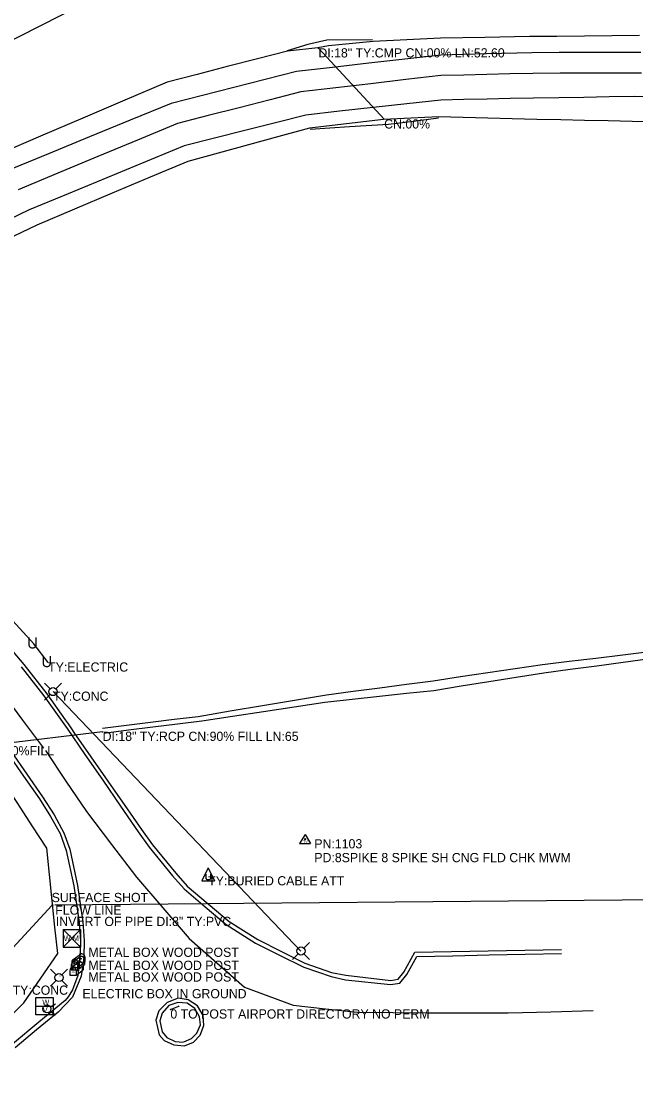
# Model space of a CAD drawing. Extents: x 1707085 to 1720058, y 548761 to 560063.
# Drawn here: x 1711655 to 1711989, y 548951 to 549528 of the extents above; entities that cross this region are included whole.
import ezdxf

# ---------------------------------------------------------------- set-up
doc = ezdxf.new("R2010")
doc.units = 0
for name, color, linetype in [('3', 7, 'Continuous'), ('Default', 7, 'Continuous'), ('R_Draft', 7, 'Continuous'), ('R_Horz Alg Annot', 7, 'Continuous'), ('R_Water Annot', 7, 'Continuous'), ('S_CROSS_DRAIN_ANNOT', 7, 'Continuous'), ('S_CURB', 7, 'Continuous'), ('S_DRG_PT_SYM', 7, 'Continuous'), ('S_EDGE_PAVEMENT', 7, 'Continuous'), ('S_GRD_PT_SYM', 7, 'Continuous'), ('S_MAILBOX', 7, 'Continuous'), ('S_MAILBOX_ANNOT', 7, 'Continuous'), ('S_MANHOLE_ANNOT', 7, 'Continuous'), ('S_MISC_STRUCTURES_ANNOT', 7, 'Continuous'), ('S_MISC_TOPO_POINT', 7, 'Continuous'), ('S_MSC_PT_SYM', 7, 'Continuous'), ('S_PAVEMENT_CROWN', 7, 'Continuous'), ('S_SANITARY_SEWER', 7, 'Continuous'), ('S_SANITARY_SEWER_ANNOT', 7, 'Continuous'), ('S_SECONDARY_CTL_ANNOT', 7, 'Continuous'), ('S_SIDE_DRAIN_ANNOT', 7, 'Continuous'), ('S_SIGN_ANNOT', 7, 'Continuous'), ('S_UNDERGROUND_CABLE', 7, 'Continuous'), ('S_UNDERGROUND_CABLE_ANNOT', 7, 'Continuous'), ('S_UTILITY_POLE', 7, 'Continuous'), ('S_UTILITY_POLE_ANNOT', 7, 'Continuous'), ('S_UTL_PT_SYM', 7, 'Continuous')]:
    doc.layers.add(name, color=color, linetype=linetype)

msp = doc.modelspace()

# ---------------------------------------------------------------- linework, layer by layer
for points in [[(1711990.87, 549520.44), (1711975.92, 549520.28), (1711960.98, 549520.11), (1711946.04, 549519.95), (1711931.09, 549519.79), (1711906.92, 549519.41), (1711882.74, 549519.03), (1711864.5, 549518.06), (1711846.26, 549517.1), (1711821.98, 549514.8), (1711816.17, 549513.75), (1711799.76, 549511.86), (1711783.39, 549507.68), (1711767.02, 549503.49), (1711750.66, 549499.3), (1711734.29, 549495.11), (1711711.39, 549485.32), (1711688.5, 549475.53), (1711665.6, 549465.74), (1711642.7, 549455.95)], [(1711845.91, 549518.04), (1711821.14, 549517.95), (1711810.67, 549515.52), (1711799.44, 549512.16)], [(1712004.2, 549473.45), (1711986.91, 549473.71), (1711973.98, 549473.99), (1711961.05, 549474.27), (1711948.12, 549474.55), (1711935.19, 549474.82), (1711921.85, 549475.16), (1711908.5, 549475.49), (1711895.16, 549475.83), (1711881.82, 549476.16), (1711866.84, 549475.51), (1711851.86, 549474.86), (1711831.73, 549472.48), (1711811.6, 549470.1), (1711795.09, 549465.58), (1711778.57, 549461.07), (1711762.05, 549456.55), (1711745.54, 549452.04), (1711725.02, 549443.4), (1711704.51, 549434.77), (1711683.99, 549426.13), (1711663.48, 549417.49), (1711646.94, 549409.44)], [(1711881.74, 549475.45), (1711868.18, 549473.79), (1711854.61, 549472.12), (1711833.3, 549470.74), (1711812, 549469.35)], [(1711699.23, 549144.27), (1711712.22, 549145.85), (1711725.21, 549147.44), (1711738.2, 549149.02), (1711751.19, 549150.6), (1711768.63, 549153.55), (1711786.06, 549156.5), (1711803.49, 549159.45), (1711820.93, 549162.4), (1711835.42, 549164.3), (1711849.91, 549166.21), (1711864.4, 549168.11), (1711878.89, 549170.01), (1711893.72, 549172.21), (1711908.56, 549174.4), (1711923.39, 549176.6), (1711938.23, 549178.8), (1711952.76, 549180.55), (1711967.3, 549182.3), (1711981.83, 549184.05), (1711996.36, 549185.8)], [(1711699.96, 549141.57), (1711713.26, 549143.24), (1711726.56, 549144.92), (1711739.86, 549146.59), (1711753.16, 549148.27), (1711769.87, 549150.8), (1711786.58, 549153.33), (1711803.29, 549155.86), (1711819.99, 549158.39), (1711834.8, 549159.98), (1711849.61, 549161.57), (1711864.41, 549163.16), (1711879.22, 549164.75), (1711894.14, 549167.13), (1711909.05, 549169.52), (1711923.96, 549171.9), (1711938.88, 549174.28), (1711953.29, 549176.2), (1711967.7, 549178.13), (1711982.11, 549180.05), (1711996.52, 549181.97)], [(1711611.51, 548950.56), (1711622.73, 548961.7), (1711633.95, 548972.84), (1711645.16, 548983.98), (1711656.38, 548995.12), (1711665.63, 549008.46), (1711674.87, 549021.8), (1711673.4, 549036.12), (1711671.93, 549050.43), (1711670.45, 549064.75), (1711668.98, 549079.06), (1711661.08, 549091.17), (1711653.18, 549103.27), (1711645.28, 549115.38), (1711637.38, 549127.48)]]:
    msp.add_lwpolyline(points)
at = {"layer": '3'}
for p, q in [((1711816.48, 549513.49), (1711852.23, 549474.89)), ((1711699.29, 549142.3), (1711634.65, 549134.46))]:
    msp.add_line(p, q, dxfattribs=at)
at = {"layer": 'R_Draft'}
for p, q in [((1711809.29, 549086.54), (1711806.28, 549081.59)), ((1711809.29, 549086.54), (1711812.23, 549081.59)), ((1711806.28, 549081.59), (1711812.23, 549081.59))]:
    msp.add_line(p, q, dxfattribs=at)
for radius in [0.311, 0.183, 0.103]:
    msp.add_circle((1711809.29, 549083.93), radius, dxfattribs=at)
at = {"layer": 'R_Horz Alg Annot'}
msp.add_line((1711736.08, 548991.51), (1711740.62, 548993.18), dxfattribs=at)
at = {"layer": 'R_Water Annot'}
for p, q in [((1711677.92, 549034.85), (1711687.26, 549034.85)), ((1711677.92, 549034.85), (1711677.92, 549025.36)), ((1711677.92, 549034.85), (1711687.26, 549025.36)), ((1711687.26, 549034.85), (1711677.92, 549025.36)), ((1711687.26, 549034.85), (1711687.26, 549025.36)), ((1711677.92, 549025.36), (1711687.26, 549025.36)), ((1711662.94, 548997.98), (1711672.36, 548997.98)), ((1711662.94, 548988.56), (1711662.94, 548997.98)), ((1711670.93, 548992.83), (1711673.75, 548994.56)), ((1711672.36, 548997.98), (1711672.36, 548988.56)), ((1711662.94, 548993.29), (1711672.36, 548993.29)), ((1711672.36, 548988.56), (1711662.94, 548988.56)), ((1711670.81, 548990.52), (1711673.71, 548988.59))]:
    msp.add_line(p, q, dxfattribs=at)
msp.add_circle((1711669.03, 548991.77), 2.18, dxfattribs=at)
at = {"layer": 'S_CURB'}
for points in [[(1711643.49, 549193.99), (1711656.55, 549178.8), (1711668.9, 549162.86), (1711679.01, 549148.77), (1711680.5, 549146.55), (1711682.42, 549143.88), (1711683.66, 549141.82), (1711692.86, 549128.64), (1711702.07, 549115.47), (1711711.27, 549102.3), (1711720.47, 549089.12), (1711726.34, 549080.94), (1711738.97, 549065.42), (1711745.16, 549058.45), (1711756.58, 549048.87), (1711768, 549039.3), (1711783.63, 549029.35), (1711796.41, 549023), (1711809.18, 549016.65), (1711823.62, 549011.55), (1711831.39, 549009.99), (1711855.77, 549007.12), (1711859.78, 549007.86), (1711862.83, 549011.68), (1711868.88, 549022.61), (1711888.8, 549022.97), (1711908.72, 549023.34), (1711928.64, 549023.71), (1711948.55, 549024.08)], [(1711647.77, 549130.54), (1711656.35, 549118.18), (1711664.93, 549105.82), (1711670.98, 549096.33), (1711676.24, 549086.98), (1711679.53, 549077.84), (1711683.59, 549058.51), (1711686.44, 549038.73), (1711687.17, 549028.74), (1711686.91, 549019.68), (1711685.72, 549009.93), (1711682.92, 549002.12), (1711681.49, 548999.76), (1711680.6, 548998.23), (1711678.97, 548996.32), (1711664.62, 548984.47), (1711650.28, 548972.62)], [(1711743.41, 548973.85), (1711747.61, 548975.66), (1711750.46, 548978.48), (1711752.39, 548983.04), (1711751.99, 548987.44), (1711749.43, 548991.89), (1711745.12, 548994.78), (1711740.05, 548995.29), (1711735.3, 548993.56), (1711731.57, 548989.46), (1711730.29, 548985.31), (1711731.58, 548979.24), (1711734.18, 548976.17), (1711738.72, 548973.98), (1711743.06, 548973.69)]]:
    msp.add_lwpolyline(points, dxfattribs=at)
at = {"layer": 'S_DRG_PT_SYM'}
for points in [[(1711816.48, 549513.49), (1711816.48, 549513.54), (1711816.48, 549513.49), (1711816.43, 549513.49), (1711816.48, 549513.49), (1711816.48, 549513.44), (1711816.48, 549513.49), (1711816.53, 549513.49)], [(1711852.23, 549474.89), (1711852.23, 549474.94), (1711852.23, 549474.89), (1711852.18, 549474.89), (1711852.23, 549474.89), (1711852.23, 549474.84), (1711852.23, 549474.89), (1711852.28, 549474.89)], [(1711699.29, 549142.3), (1711699.29, 549142.35), (1711699.29, 549142.3), (1711699.24, 549142.3), (1711699.29, 549142.3), (1711699.29, 549142.25), (1711699.29, 549142.3), (1711699.34, 549142.3)]]:
    msp.add_lwpolyline(points, dxfattribs=at)
at = {"layer": 'S_EDGE_PAVEMENT'}
for points in [[(1711991.65, 549511.21), (1711976.87, 549511.17), (1711962.09, 549511.13), (1711947.31, 549511.09), (1711932.53, 549511.05), (1711907.8, 549510.43), (1711883.06, 549509.81), (1711863.45, 549507.57), (1711843.83, 549505.32), (1711824.22, 549503.07), (1711804.61, 549500.83), (1711787.58, 549496.52), (1711770.54, 549492.2), (1711753.51, 549487.89), (1711736.48, 549483.57), (1711714.29, 549474.46), (1711692.1, 549465.34), (1711669.9, 549456.22), (1711647.71, 549447.1)], [(1711991.65, 549511.21), (1711976.87, 549511.17), (1711962.09, 549511.13), (1711947.31, 549511.09), (1711932.53, 549511.05), (1711907.8, 549510.43), (1711883.06, 549509.81), (1711863.45, 549507.57), (1711843.83, 549505.32), (1711824.22, 549503.07), (1711804.61, 549500.83), (1711787.58, 549496.52), (1711770.54, 549492.2), (1711753.51, 549487.89), (1711736.48, 549483.57), (1711714.29, 549474.46), (1711692.1, 549465.34), (1711669.9, 549456.22), (1711647.71, 549447.1)], [(1712004.79, 549487.15), (1711988.04, 549487.23), (1711974.37, 549487.02), (1711960.71, 549486.81), (1711947.04, 549486.59), (1711933.37, 549486.38), (1711920.76, 549486.12), (1711908.15, 549485.86), (1711895.54, 549485.61), (1711882.94, 549485.35), (1711864.61, 549483.31), (1711846.28, 549481.27), (1711827.96, 549479.23), (1711809.63, 549477.19), (1711793.12, 549473.02), (1711776.6, 549468.85), (1711760.09, 549464.68), (1711743.58, 549460.51), (1711722.54, 549451.81), (1711701.51, 549443.1), (1711680.47, 549434.39), (1711659.43, 549425.69), (1711643, 549417.91)], [(1712004.79, 549487.15), (1711988.04, 549487.23), (1711974.37, 549487.02), (1711960.71, 549486.81), (1711947.04, 549486.59), (1711933.37, 549486.38), (1711920.76, 549486.12), (1711908.15, 549485.86), (1711895.54, 549485.61), (1711882.94, 549485.35), (1711864.61, 549483.31), (1711846.28, 549481.27), (1711827.96, 549479.23), (1711809.63, 549477.19), (1711793.12, 549473.02), (1711776.6, 549468.85), (1711760.09, 549464.68), (1711743.58, 549460.51), (1711722.54, 549451.81), (1711701.51, 549443.1), (1711680.47, 549434.39), (1711659.43, 549425.69), (1711643, 549417.91)], [(1711655.07, 549177.46), (1711667.27, 549161.8), (1711679.95, 549144.01), (1711689.62, 549129.98), (1711699.3, 549115.95), (1711708.97, 549101.92), (1711718.65, 549087.89), (1711724.51, 549079.61), (1711737.29, 549064.07), (1711743.56, 549057.03), (1711754.93, 549047.27), (1711766.31, 549037.51), (1711782.34, 549027.48), (1711795.43, 549020.97), (1711808.51, 549014.46), (1711823.52, 549009.4), (1711831.16, 549007.62), (1711855.6, 549004.99), (1711860.69, 549005.72), (1711864.58, 549010.42), (1711869.98, 549020.25), (1711889.61, 549020.66), (1711909.24, 549021.07), (1711928.87, 549021.48), (1711948.5, 549021.89)], [(1711649.62, 549131.57), (1711658.16, 549119.26), (1711666.7, 549106.96), (1711672.87, 549097.14), (1711678.17, 549087.42), (1711681.43, 549078.5), (1711685.63, 549058.79), (1711688.57, 549038.95), (1711689.2, 549028.92), (1711689.03, 549019.62), (1711687.63, 549009.61), (1711682.91, 548998.14), (1711675.11, 548989.89), (1711663.4, 548980.29), (1711651.69, 548970.68)]]:
    msp.add_lwpolyline(points, dxfattribs=at)
msp.add_lwpolyline([(1711743.71, 548971.66), (1711748.56, 548973.66), (1711752.34, 548977.43), (1711754.29, 548982.69), (1711753.83, 548988.19), (1711750.73, 548993.48), (1711745.73, 548996.7), (1711740.37, 548997.53), (1711734.33, 548995.26), (1711729.89, 548990.66), (1711728.18, 548985.56), (1711729.9, 548977.73), (1711732.78, 548974.64), (1711737.87, 548972.17)], close=True, dxfattribs=at)
at = {"layer": 'S_GRD_PT_SYM'}
for points in [[(1711671.61, 549047.9), (1711671.61, 549047.95), (1711671.61, 549047.9), (1711671.56, 549047.9), (1711671.61, 549047.9), (1711671.61, 549047.85), (1711671.61, 549047.9), (1711671.66, 549047.9)], [(1711673.3, 549048.29), (1711673.3, 549048.34), (1711673.3, 549048.29), (1711673.25, 549048.29), (1711673.3, 549048.29), (1711673.3, 549048.24), (1711673.3, 549048.29), (1711673.35, 549048.29)]]:
    msp.add_lwpolyline(points, dxfattribs=at)
at = {"layer": 'S_MAILBOX'}
for p, q in [((1711682.08, 549013.97), (1711686.22, 549017.08)), ((1711682.49, 549017.04), (1711682.49, 549014.32)), ((1711682.78, 549016.94), (1711686.91, 549020.04)), ((1711683.05, 549018.31), (1711687.18, 549021.42)), ((1711685.82, 549014.32), (1711689.61, 549017.23)), ((1711685.82, 549017.04), (1711685.82, 549014.32)), ((1711686.39, 549018.22), (1711686.39, 549015.51)), ((1711686.66, 549019.6), (1711686.66, 549016.89)), ((1711689.34, 549018.57), (1711689.34, 549015.86)), ((1711689.61, 549019.95), (1711689.61, 549017.23)), ((1711681.53, 549012.69), (1711681.53, 549009.98)), ((1711682.22, 549015.66), (1711682.22, 549012.95)), ((1711682.22, 549012.95), (1711685.55, 549012.95)), ((1711682.49, 549014.32), (1711685.82, 549014.32)), ((1711684.85, 549009.98), (1711688.65, 549012.89)), ((1711684.85, 549012.69), (1711684.85, 549009.98)), ((1711685.55, 549012.95), (1711689.34, 549015.86)), ((1711685.55, 549015.66), (1711685.55, 549012.95)), ((1711685.7, 549015.26), (1711685.7, 549012.54)), ((1711688.65, 549015.6), (1711688.65, 549012.89)), ((1711681.53, 549009.98), (1711684.85, 549009.98))]:
    msp.add_line(p, q, dxfattribs=at)
for points in [[(1711683.68, 549018.15), (1711683.9, 549018.02), (1711683.9, 549017.63), (1711684.2, 549017.63), (1711684.2, 549017.99), (1711684.01, 549018.24), (1711683.68, 549018.18)], [(1711686.39, 549018.22), (1711687.5, 549017.56), (1711686.39, 549017.21)], [(1711686.66, 549019.6), (1711687.77, 549018.94), (1711686.66, 549018.59)], [(1711682.71, 549013.81), (1711682.93, 549013.67), (1711682.93, 549013.28), (1711683.24, 549013.28), (1711683.24, 549013.64), (1711683.04, 549013.89), (1711682.71, 549013.84)], [(1711683.41, 549016.78), (1711683.63, 549016.64), (1711683.63, 549016.25), (1711683.94, 549016.25), (1711683.94, 549016.61), (1711683.74, 549016.86), (1711683.41, 549016.8)], [(1711685.7, 549015.26), (1711686.81, 549014.59), (1711685.7, 549014.24)]]:
    msp.add_lwpolyline(points, dxfattribs=at)
for centre, end in [((1711683.89, 549015.66), 180), ((1711684.16, 549017.04), 180), ((1711686.99, 549015.6), 117.57184), ((1711687.68, 549018.57), 117.57184), ((1711687.95, 549019.95), 117.57184), ((1711683.19, 549012.69), 180)]:
    msp.add_arc(centre, 1.66, 0, end, dxfattribs=at)
for centre in [(1711686.66, 549016.89), (1711685.7, 549012.54), (1711686.39, 549015.51)]:
    msp.add_ellipse(centre, major_axis=(0.145, 0.132), ratio=0.564646, dxfattribs=at)
at = {"layer": 'S_MSC_PT_SYM'}
for points in [[(1711676.11, 549009.72), (1711676.11, 549009.77), (1711676.11, 549009.72), (1711676.06, 549009.72), (1711676.11, 549009.72), (1711676.11, 549009.67), (1711676.11, 549009.72), (1711676.16, 549009.72)], [(1711736.08, 548991.51), (1711736.08, 548991.56), (1711736.08, 548991.51), (1711736.03, 548991.51), (1711736.08, 548991.51), (1711736.08, 548991.46), (1711736.08, 548991.51), (1711736.13, 548991.51)], [(1711740.62, 548993.18), (1711740.62, 548993.23), (1711740.62, 548993.18), (1711740.57, 548993.18), (1711740.62, 548993.18), (1711740.62, 548993.13), (1711740.62, 548993.18), (1711740.67, 548993.18)]]:
    msp.add_lwpolyline(points, dxfattribs=at)
at = {"layer": 'S_PAVEMENT_CROWN'}
for points in [[(1711991.98, 549500.01), (1711977.24, 549499.96), (1711962.49, 549499.91), (1711947.75, 549499.87), (1711933.01, 549499.82), (1711920.51, 549499.53), (1711908.01, 549499.24), (1711895.51, 549498.95), (1711883.01, 549498.66), (1711864.01, 549496.46), (1711845.02, 549494.25), (1711826.02, 549492.05), (1711807.02, 549489.84), (1711790.24, 549485.52), (1711773.46, 549481.21), (1711756.68, 549476.89), (1711739.89, 549472.57), (1711718.26, 549463.6), (1711696.62, 549454.62), (1711674.98, 549445.65), (1711653.34, 549436.67)], [(1711991.98, 549500.01), (1711977.24, 549499.96), (1711962.49, 549499.91), (1711947.75, 549499.87), (1711933.01, 549499.82), (1711920.51, 549499.53), (1711908.01, 549499.24), (1711895.51, 549498.95), (1711883.01, 549498.66), (1711864.01, 549496.46), (1711845.02, 549494.25), (1711826.02, 549492.05), (1711807.02, 549489.84), (1711790.24, 549485.52), (1711773.46, 549481.21), (1711756.68, 549476.89), (1711739.89, 549472.57), (1711718.26, 549463.6), (1711696.62, 549454.62), (1711674.98, 549445.65), (1711653.34, 549436.67)], [(1711667.36, 549133.3), (1711656.01, 549148.51), (1711644.65, 549163.71), (1711630.91, 549179.29), (1711617.17, 549194.86), (1711601.32, 549209.79), (1711585.47, 549224.73), (1711572.48, 549234.65), (1711559.48, 549244.56), (1711544.08, 549252.09), (1711528.67, 549259.63), (1711507.77, 549266.39), (1711486.86, 549273.16), (1711466.8, 549279.19), (1711446.73, 549285.22)], [(1711668.15, 549132.08), (1711679.37, 549115.48), (1711690.58, 549098.88), (1711704.14, 549081.04), (1711717.7, 549063.21), (1711731.98, 549046.63), (1711746.26, 549030.04), (1711761.34, 549016.82), (1711776.42, 549003.6), (1711789.63, 548998.65), (1711802.84, 548993.7), (1711820.28, 548991.84), (1711837.73, 548989.98), (1711856.98, 548989.79), (1711876.23, 548989.6), (1711897.95, 548989.61), (1711919.67, 548989.62), (1711942.68, 548990.21), (1711965.7, 548990.81)]]:
    msp.add_lwpolyline(points, dxfattribs=at)
at = {"layer": 'S_SANITARY_SEWER'}
for p, q in [((1711673.3, 549048.29), (1712062.72, 549051.79)), ((1711671.61, 549047.9), (1711589.69, 548959.11))]:
    msp.add_line(p, q, dxfattribs=at)
at = {"layer": 'S_UNDERGROUND_CABLE'}
for p, q in [((1711669.69, 549179.92), (1711661.93, 549190.04)), ((1711672.35, 549164.08), (1711807.02, 549023.17)), ((1711756.64, 549068.37), (1711753.11, 549061.27)), ((1711755.44, 549062.51), (1711755.44, 549064.96)), ((1711756.64, 549068.37), (1711760.13, 549061.27)), ((1711757.8, 549064.96), (1711757.8, 549062.51)), ((1711753.11, 549061.27), (1711760.13, 549061.27)), ((1711756.06, 549061.86), (1711755.44, 549062.51)), ((1711757.26, 549061.86), (1711756.06, 549061.86)), ((1711757.8, 549062.51), (1711757.26, 549061.86))]:
    msp.add_line(p, q, dxfattribs=at)
msp.add_lwpolyline([(1711661.93, 549190.04), (1711609.23, 549247.35), (1711526.12, 549292.13)], dxfattribs=at)
at = {"layer": 'S_UTILITY_POLE'}
for p, q in [((1711670.75, 549165.66), (1711667.77, 549168.65)), ((1711673.93, 549165.66), (1711676.91, 549168.65)), ((1711670.75, 549162.48), (1711667.77, 549159.5)), ((1711673.93, 549162.48), (1711676.91, 549159.5)), ((1711805.42, 549024.75), (1711802.44, 549027.74)), ((1711808.6, 549024.75), (1711811.59, 549027.74)), ((1711805.42, 549021.58), (1711802.44, 549018.59)), ((1711808.6, 549021.58), (1711811.59, 549018.59)), ((1711673.95, 549010.34), (1711670.97, 549013.32)), ((1711677.13, 549010.34), (1711680.11, 549013.32)), ((1711673.95, 549007.16), (1711670.97, 549004.18)), ((1711677.13, 549007.16), (1711680.11, 549004.18))]:
    msp.add_line(p, q, dxfattribs=at)
msp.add_lwpolyline([(1711064.39, 549251.72), (1711313.01, 549347.35), (1711526.73, 549455.46), (1711746.33, 549566.96), (1712411.7, 549904.79), (1712500.91, 549949.57)], dxfattribs=at)
for centre in [(1711672.35, 549164.08), (1711807.02, 549023.17), (1711675.55, 549008.76)]:
    msp.add_circle(centre, 2.21, dxfattribs=at)
at = {"layer": 'S_UTL_PT_SYM'}
for points in [[(1711671.61, 549047.9), (1711671.61, 549047.95), (1711671.61, 549047.9), (1711671.56, 549047.9), (1711671.61, 549047.9), (1711671.61, 549047.85), (1711671.61, 549047.9), (1711671.66, 549047.9)], [(1711672.29, 549048.19), (1711672.29, 549048.24), (1711672.29, 549048.19), (1711672.24, 549048.19), (1711672.29, 549048.19), (1711672.29, 549048.14), (1711672.29, 549048.19), (1711672.34, 549048.19)], [(1711673.3, 549048.29), (1711673.3, 549048.34), (1711673.3, 549048.29), (1711673.25, 549048.29), (1711673.3, 549048.29), (1711673.3, 549048.24), (1711673.3, 549048.29), (1711673.35, 549048.29)]]:
    msp.add_lwpolyline(points, dxfattribs=at)

# ---------------------------------------------------------------- texts
at = {"layer": 'Default'}
for p in [(1711658.3, 549187.49), (1711666.06, 549177.37)]:
    msp.add_text('U', height=6, rotation=360, dxfattribs=at).set_placement(p)
at = {"layer": 'R_Draft'}
msp.add_text('TV', height=1.5, rotation=360, dxfattribs=at).set_placement((1711808.08, 549081.92))
at = {"layer": 'R_Water Annot'}
for s, p in [('W M', (1711678.13, 549028.62)), ('W', (1711666.49, 548993.82)), ('V', (1711666.73, 548989.76))]:
    msp.add_text(s, height=3, rotation=360, dxfattribs=at).set_placement(p)
at = {"layer": 'S_CROSS_DRAIN_ANNOT'}
for s, p in [('DI:18" TY:CMP CN:00% LN:52.60', (1711816.48, 549508.49)), ('CN:00%', (1711852.23, 549469.89))]:
    msp.add_text(s, height=5, dxfattribs=at).set_placement(p)
at = {"layer": 'S_MAILBOX'}
for p in [(1711682.29, 549011.17), (1711682.99, 549014.14), (1711683.26, 549015.52)]:
    msp.add_text('US', height=0.96, rotation=360, dxfattribs=at).set_placement(p)
at = {"layer": 'S_MAILBOX_ANNOT'}
for p in [(1711691.52, 549020.01), (1711691.52, 549012.93), (1711691.52, 549006.58)]:
    msp.add_text('METAL BOX WOOD POST', height=5, dxfattribs=at).set_placement(p)
at = {"layer": 'S_MANHOLE_ANNOT'}
msp.add_text('FLOW LINE', height=5, dxfattribs=at).set_placement((1711673.55, 549042.91))
at = {"layer": 'S_MISC_STRUCTURES_ANNOT'}
msp.add_text('ELECTRIC BOX IN GROUND', height=5, dxfattribs=at).set_placement((1711688.32, 548997.52))
at = {"layer": 'S_MISC_TOPO_POINT'}
msp.add_text('SURFACE SHOT', height=5, dxfattribs=at).set_placement((1711671.59, 549049.76))
at = {"layer": 'S_SANITARY_SEWER_ANNOT'}
msp.add_text('INVERT OF PIPE DI:8" TY:PVC', height=5, dxfattribs=at).set_placement((1711673.86, 549036.76))
at = {"layer": 'S_SECONDARY_CTL_ANNOT'}
for s, p in [('PN:1103', (1711814.29, 549078.93)), ('PD:8SPIKE 8 SPIKE SH CNG FLD CHK MWM', (1711814.29, 549071.43))]:
    msp.add_text(s, height=5, dxfattribs=at).set_placement(p)
at = {"layer": 'S_SIDE_DRAIN_ANNOT'}
for s, p in [('DI:18" TY:RCP CN:90% FILL LN:65', (1711699.29, 549137.3)), ('CN:00%FILL', (1711634.65, 549129.46))]:
    msp.add_text(s, height=5, dxfattribs=at).set_placement(p)
at = {"layer": 'S_SIGN_ANNOT'}
msp.add_text('0 TO POST AIRPORT DIRECTORY NO PERM', height=5, dxfattribs=at).set_placement((1711736.08, 548986.51))
at = {"layer": 'S_UNDERGROUND_CABLE_ANNOT'}
msp.add_text('TY:ELECTRIC', height=5, dxfattribs=at).set_placement((1711669.69, 549174.92))
at = {"layer": 'S_UTILITY_POLE_ANNOT'}
for s, p in [('TY:CONC', (1711672.35, 549159.08)), ('TY:BURIED CABLE ATT', (1711756.64, 549058.83)), ('TY:CONC', (1711650.4, 548999.43))]:
    msp.add_text(s, height=5, dxfattribs=at).set_placement(p)

doc.saveas('drawing.dxf')
